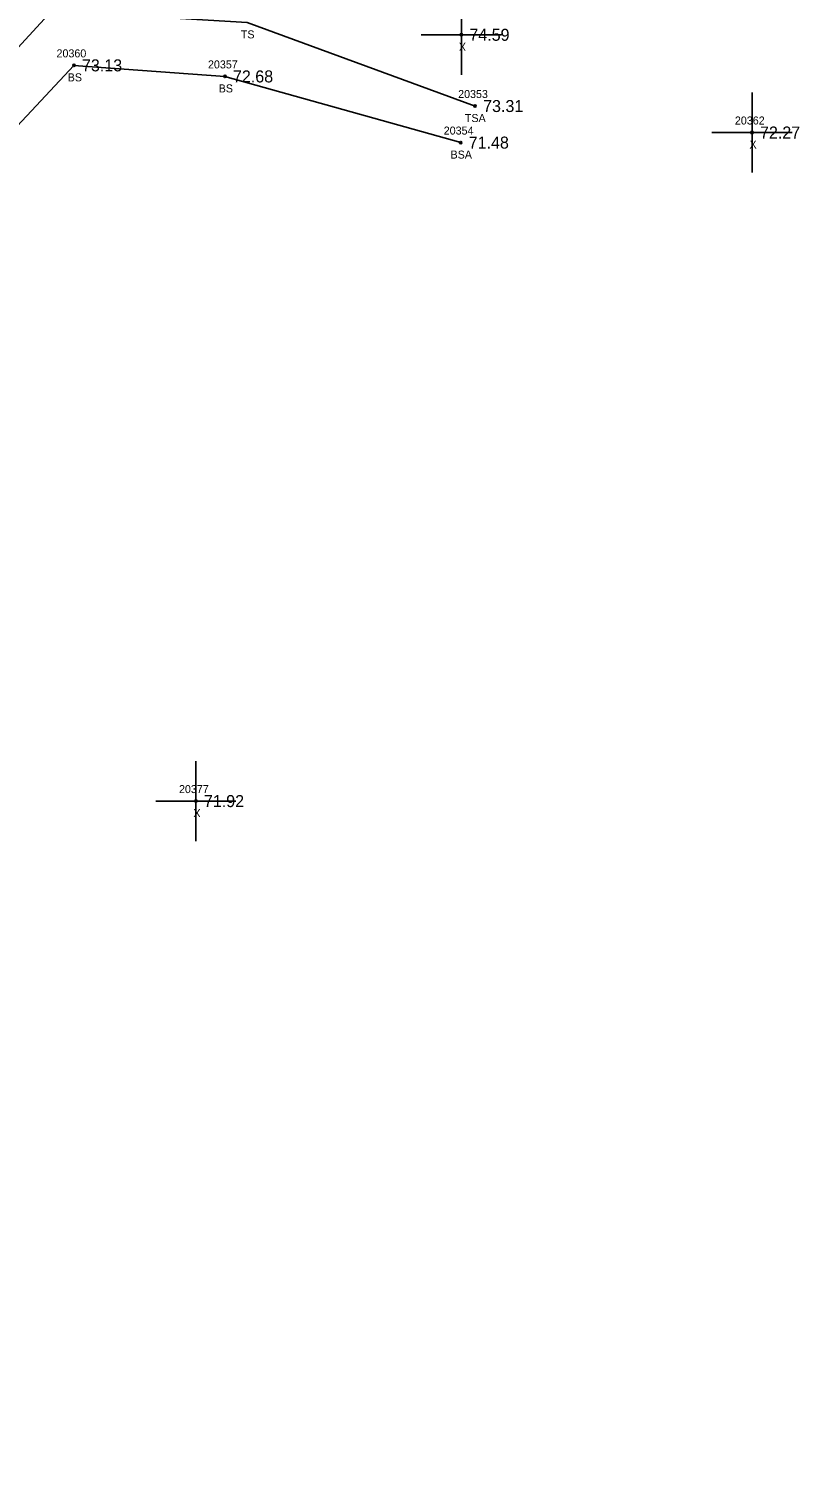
# Model space of a CAD drawing. Extents: x 2505300 to 2506184, y 912965 to 913825.
# Drawn here: x 2505552.8 to 2505649.1, y 913028.1 to 913206.7 of the extents above; entities that cross this region are included whole.
import ezdxf

# ---------------------------------------------------------------- set-up
doc = ezdxf.new("R2010")
doc.units = 0
for name, color, linetype in [('RD_DTM_BkLn2', 7, 'Continuous'), ('RD_DTM_BkLn_txCode', 7, 'Continuous'), ('RD_EX_Misc', 7, 'Continuous'), ('RD_EX_Misc_txCode', 7, 'Continuous'), ('RD_EX_TX_Misc_ELEV', 7, 'Continuous'), ('RD_SMD_Locator', 7, 'Continuous')]:
    doc.layers.add(name, color=color, linetype=linetype)

msp = doc.modelspace()

# ---------------------------------------------------------------- linework, layer by layer
at = {"layer": 'RD_DTM_BkLn2'}
for points in [[(2505608.57, 913197.02), (2505580.09, 913207.47), (2505555.7, 913208.91), (2505524.48, 913174.98), (2505452.19, 913104.88), (2505378.2, 913033.83)], [(2505606.77, 913192.45), (2505577.32, 913200.72), (2505558.46, 913202.1), (2505528.34, 913169.89), (2505451.24, 913096.03), (2505383.47, 913028.12)]]:
    msp.add_lwpolyline(points, dxfattribs=at)
at = {"layer": 'RD_EX_Misc'}
for p, q in [((2505606.85, 913200.92), (2505606.85, 913210.92)), ((2505601.85, 913205.92), (2505611.85, 913205.92)), ((2505643.16, 913188.71), (2505643.16, 913198.71)), ((2505638.16, 913193.71), (2505648.16, 913193.71)), ((2505573.69, 913105.15), (2505573.69, 913115.15)), ((2505568.69, 913110.15), (2505578.69, 913110.15))]:
    msp.add_line(p, q, dxfattribs=at)
at = {"layer": 'RD_SMD_Locator'}
for centre in [(2505606.85, 913205.92), (2505558.46, 913202.1), (2505577.32, 913200.72), (2505608.57, 913197.02), (2505643.16, 913193.71), (2505606.77, 913192.45), (2505573.69, 913110.15)]:
    msp.add_circle(centre, 0.15, dxfattribs=at)

# ---------------------------------------------------------------- texts
at = {"layer": 'RD_DTM_BkLn_txCode'}
for s, p in [('TS', (2505579.3, 913205.47)), ('20360', (2505556.28, 913203.1)), ('20357', (2505575.2, 913201.72)), ('BS', (2505557.68, 913200.1)), ('BS', (2505576.54, 913198.72)), ('20353', (2505606.45, 913198.02)), ('TSA', (2505607.29, 913195.02)), ('20354', (2505604.65, 913193.45)), ('BSA', (2505605.5, 913190.45))]:
    msp.add_text(s, height=1, dxfattribs=at).set_placement(p)
at = {"layer": 'RD_EX_Misc_txCode'}
for s, p in [('X', (2505606.54, 913203.92)), ('20362', (2505641.02, 913194.71)), ('X', (2505642.85, 913191.71)), ('20377', (2505571.58, 913111.15)), ('X', (2505573.38, 913108.15))]:
    msp.add_text(s, height=1, dxfattribs=at).set_placement(p)
at = {"layer": 'RD_EX_TX_Misc_ELEV'}
for s, p in [('74.59', (2505607.85, 913205.17)), ('73.13', (2505559.46, 913201.35)), ('72.68', (2505578.32, 913199.97)), ('73.31', (2505609.57, 913196.27)), ('72.27', (2505644.16, 913192.96)), ('71.48', (2505607.77, 913191.7)), ('71.92', (2505574.69, 913109.4))]:
    msp.add_text(s, height=1.5, dxfattribs=at).set_placement(p)

doc.saveas('drawing.dxf')
